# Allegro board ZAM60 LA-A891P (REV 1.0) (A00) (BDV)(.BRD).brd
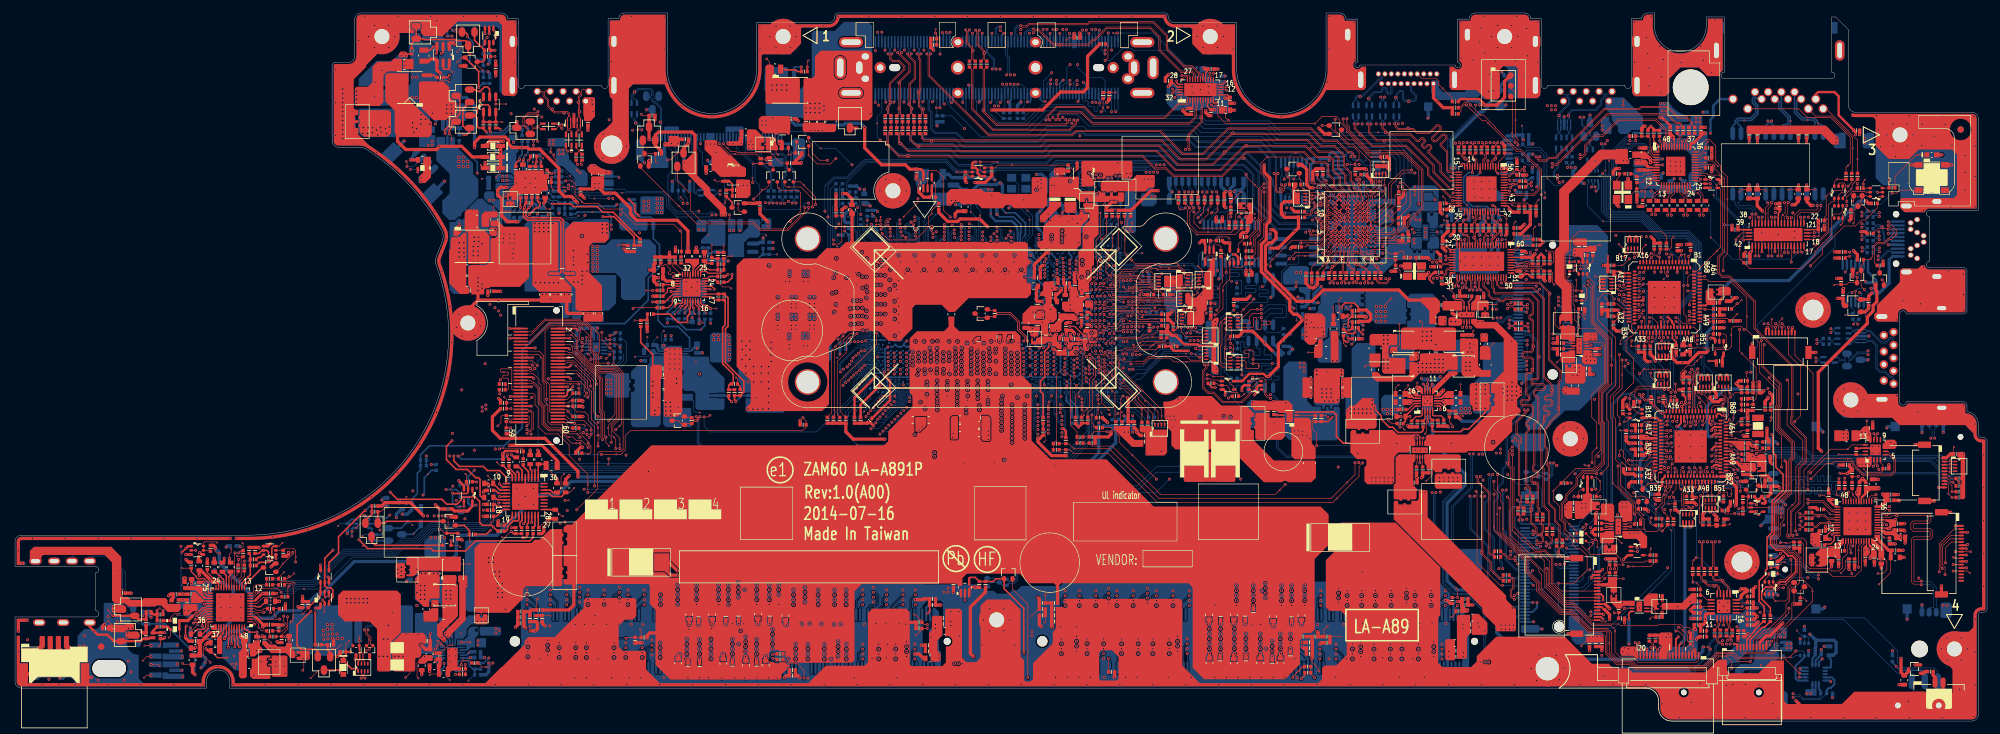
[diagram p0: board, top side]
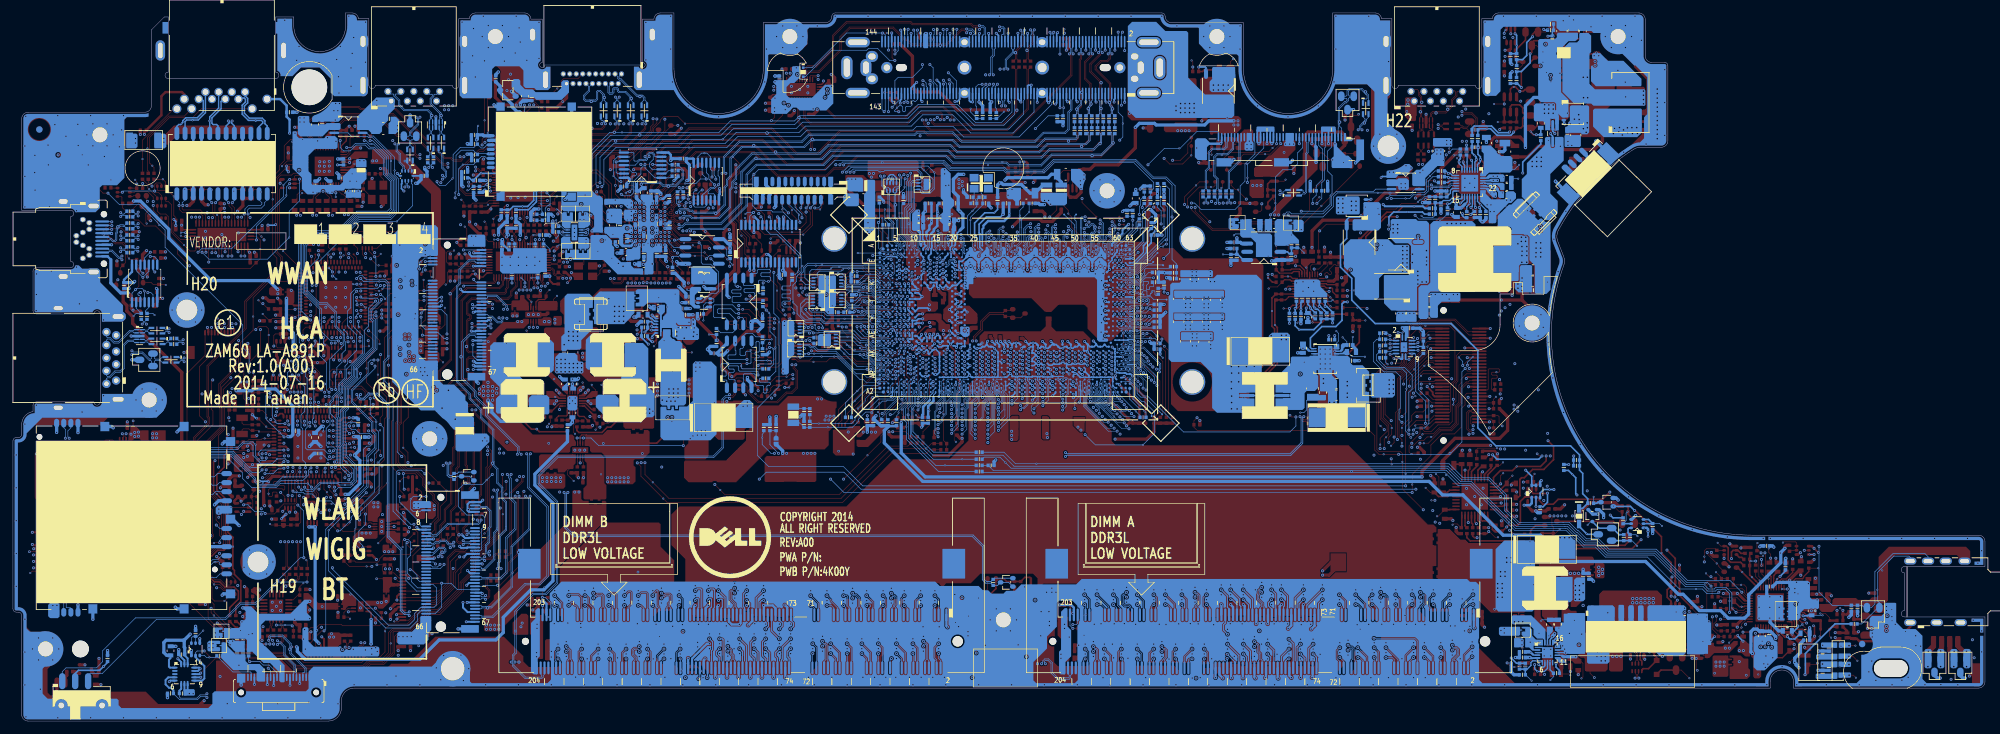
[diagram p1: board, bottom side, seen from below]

Outline 304.75 x 109.5 mm; copper layers: TOP, GND1, IN1, VCC, IN2, IN3, GND2, IN4, GND3, BOTTOM. Coordinates in mm from the lower left corner of the outline.
Outline path: 0,27.75 0,23.9 12.45,23.9 arc(12.95,23.4) 12.45,22.9 12.45,17.1 arc(12.95,16.6) 12.45,16.1 0,16.1 0,6.1 arc(0.29,5.39) 1,5.1 29.6,5.1 29.6,6.1 arc(31.4,7.9) 33.2,6.1 33.2,5.1 252,5.1 arc(253.41,4.51) 254,3.1 254,2 arc(254.59,0.59) 256,0 302.4,0 arc(303.11,0.29) 303.4,1 303.4,16.35 arc(303.55,16.7) 303.9,16.85 304.25,16.85 arc(304.6,16.99) 304.75,17.35 304.75,43.34 arc(304.6,43.69) 304.25,43.84 303.9,43.84 arc(303.55,43.99) 303.4,44.34 303.4,45.87 arc(302.9,47.19) 301.65,47.85 301.65,48.88 arc(301.49,49.21) 301.15,49.35 292.25,49.35 arc(291.75,48.85) 291.25,49.35 291.25,62.95 arc(291.75,63.45) 292.25,62.95 301.15,62.95 arc(301.5,63.1) 301.65,63.45 301.65,69.6 arc(301.5,69.95) 301.15,70.1 295.85,70.1 arc(295.35,70.6) 295.85,71.1 295.85,78 arc(295.35,78.5) 295.85,79 303.4,79 303.4,93.15 arc(303.11,93.86) 302.4,94.15 284.35,94.15 arc(283.64,94.44) 283.35,95.15 283.35,106.88 281.35,108.88 280.75,108.88 280.75,100.35 arc(281.25,99.87) 280.8,99.35 arc(280.77,99.35) 280.75,99.35 264.15,99.35 arc(264.13,99.35) 264.1,99.35 arc(263.65,99.87) 264.15,100.35 264.15,108.88 261.35,108.88 261.35,107.5 arc(257.35,103.5) 253.35,107.5 253.35,109.5 252.34,109.5 arc(251.67,109.24) 251.35,108.6 249.75,108.6 249.75,98.3 arc(249.25,97.8) 248.75,98.3 236.85,98.3 arc(236.35,97.8) 235.85,98.3 235.85,108.6 234.25,108.6 arc(233.93,109.24) 233.25,109.5 225.7,109.5 arc(225.01,109.22) 224.7,108.55 222.95,108.55 222.95,101.85 arc(223.23,101.17) 222.55,101.45 207.85,101.45 arc(207.17,101.17) 207.45,101.85 207.45,108.55 205.7,108.55 arc(205.39,109.22) 204.7,109.5 202.6,109.5 202.6,100.85 arc(195.7,93.95) 188.8,100.85 188.8,108 179.2,108 arc(178.49,108.29) 178.2,109 arc(178.05,109.35) 177.7,109.5 127.2,109.5 arc(126.85,109.35) 126.7,109 arc(126.41,108.29) 125.7,108 114.6,108 114.6,100.85 arc(107.7,93.95) 100.8,100.85 100.8,109.5 94.24,109.5 arc(93.57,109.24) 93.25,108.6 91.65,108.6 91.65,98.3 arc(91.15,97.8) 90.65,98.3 78.75,98.3 arc(78.25,97.8) 77.75,98.3 77.75,108.6 76.15,108.6 arc(75.83,109.24) 75.15,109.5 53.5,109.5 arc(52.79,109.21) 52.5,108.5 52.5,102.85 arc(52.21,102.14) 51.5,101.85 49.5,101.85 arc(49.15,101.7) 49,101.35 49,89.73 arc(49.29,89.03) 50,88.73 53.2,88.73 arc(53.76,88.65) 54.28,88.42 arc(60.9,82.9) 65.92,75.89 arc(66.16,75.07) 66.03,74.22 65.11,71.85 arc(64.98,71.14) 65.1,70.44 arc(61.42,42.01) 36,28.75 1,28.75 arc(0.29,28.46) 0,27.75

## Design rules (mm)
net group 10: nets SPI_DO64 SPI_PCH_DO2_64
net group 12: nets PCH_OPI_COMP PCH_PCIE_RCOMP
net group 20: nets SPI_PCH_CLK TDI_IREF
net group CLK_PCIE_LAN: nets CLK_PCIE_LAN CLK_PCIE_LAN#
net group CLK_PCIE_MMI: nets CLK_PCIE_MMI CLK_PCIE_MMI#
net group CLK_PCIE_SATA: nets CLK_PCIE_SATA CLK_PCIE_SATA#
net group CLK_PCIE_WIGIG: nets CLK_PCIE_WIGIG CLK_PCIE_WIGIG#
net group CLK_PCIE_WLAN: nets CLK_PCIE_WLAN CLK_PCIE_WLAN#
net group CPU_DPB_AUX: nets CPU_DPB_AUX CPU_DPB_AUX#
net group CPU_DPC_AUX: nets CPU_DPC_AUX CPU_DPC_AUX#
net group CPU_DPC_AUX_C: nets CPU_DPC_AUX#_C CPU_DPC_AUX_C
net group CRT-SYNC: nets HSYNC_DOCK VSYNC_DOCK
net group DDR_A_DQS0: nets DDR_A_DQS0 DDR_A_DQS#0
net group DDR_A_DQS1: nets DDR_A_DQS1 DDR_A_DQS#1
net group DDR_A_DQS2: nets DDR_A_DQS2 DDR_A_DQS#2
net group DDR_A_DQS3: nets DDR_A_DQS3 DDR_A_DQS#3
net group DDR_A_DQS4: nets DDR_A_DQS4 DDR_A_DQS#4
net group DDR_A_DQS5: nets DDR_A_DQS5 DDR_A_DQS#5
net group DDR_A_DQS6: nets DDR_A_DQS6 DDR_A_DQS#6
net group DDR_A_DQS7: nets DDR_A_DQS7 DDR_A_DQS#7
net group DDR_B_DQS0: nets DDR_B_DQS0 DDR_B_DQS#0
net group DDR_B_DQS1: nets DDR_B_DQS1 DDR_B_DQS#1
net group DDR_B_DQS2: nets DDR_B_DQS2 DDR_B_DQS#2
net group DDR_B_DQS3: nets DDR_B_DQS3 DDR_B_DQS#3
net group DDR_B_DQS4: nets DDR_B_DQS4 DDR_B_DQS#4
net group DDR_B_DQS5: nets DDR_B_DQS5 DDR_B_DQS#5
net group DDR_B_DQS6: nets DDR_B_DQS6 DDR_B_DQS#6
net group DDR_B_DQS7: nets DDR_B_DQS7 DDR_B_DQS#7
net group DOCK_DCIN_IS: nets DOCK_DCIN_IS+ DOCK_DCIN_IS-
net group DOCK_USB3R1: nets DOCK_USB3RN1 DOCK_USB3RP1
net group DOCK_USB3T1: nets DOCK_USB3TN1 DOCK_USB3TP1
net group DOCK_USBP0: nets DOCK_USBP0+ DOCK_USBP0-
net group DOCK_USBP3: nets DOCK_USBP3+ DOCK_USBP3-
net group EDP_CPU_AUX_C: nets EDP_CPU_AUX#_C EDP_CPU_AUX_C
net group M_CLK_DDR0: nets M_CLK_DDR0 M_CLK_DDR#0
net group M_CLK_DDR1: nets M_CLK_DDR1 M_CLK_DDR#1
net group M_CLK_DDR2: nets M_CLK_DDR2 M_CLK_DDR#2
net group M_CLK_DDR3: nets M_CLK_DDR3 M_CLK_DDR#3
net group MDP_AUX_C: nets MDP_AUX#_C MDP_AUX_C
net group MEM_SMB: nets MEM_SMBCLK MEM_SMBDATA
net group PS8338_0: nets PS8338_N0 PS8338_P0
net group PS8338_0_C: nets PS8338_N0_C PS8338_P0_C
net group PS8338_1: nets PS8338_N1 PS8338_P1
net group PS8338_1_C: nets PS8338_N1_C PS8338_P1_C
net group PS8338_2: nets PS8338_N2 PS8338_P2
net group PS8338_2_C: nets PS8338_N2_C PS8338_P2_C
net group PS8338_3: nets PS8338_N3 PS8338_P3
net group PS8338_3_C: nets PS8338_N3_C PS8338_P3_C
net group PS8338_AUX: nets PS8338_AUX PS8338_AUX#
net group PS_USBP1_D: nets PS_USBP1_D+ PS_USBP1_D-
net group SATA_PRX_DTX_1: nets SATA_PRX_DTX_N1 SATA_PRX_DTX_P1
net group SATA_PRX_DTX_1_C: nets SATA_PRX_DTX_N1_C SATA_PRX_DTX_P1_C
net group SATA_PRX_DTX_1_RP: nets SATA_PRX_DTX_N1_RP SATA_PRX_DTX_P1_RP
net group SATA_PRX_DTX_1_RP_C: nets SATA_PRX_DTX_N1_RP_C SATA_PRX_DTX_P1_RP_C
net group SATA_PTX_DRX_1: nets SATA_PTX_DRX_N1 SATA_PTX_DRX_P1
net group SATA_PTX_DRX_1_C: nets SATA_PTX_DRX_N1_C SATA_PTX_DRX_P1_C
net group SATA_PTX_DRX_1_RP: nets SATA_PTX_DRX_N1_RP SATA_PTX_DRX_P1_RP
net group SATA_PTX_DRX_1_RP_C: nets SATA_PTX_DRX_N1_RP_C SATA_PTX_DRX_P1_RP_C
net group SD/MMCDAT: nets SD/MMCDAT0 SD/MMCDAT1
net group SENSE: nets VCCSENSE VSSSENSE
net group SML0_SMB: nets SML0_SMBCLK SML0_SMBDATA
net group SML1_SMB: nets SML1_SMBCLK SML1_SMBDATA
net group SW_DPB_AUX: nets SW_DPB_AUX SW_DPB_AUX#
net group SW_DPB_AUX_C: nets SW_DPB_AUX#_C SW_DPB_AUX_C
net group SW_DPC_AUX: nets SW_DPC_AUX SW_DPC_AUX#
net group SW_DPC_AUX_C: nets SW_DPC_AUX#_C SW_DPC_AUX_C
net group SW_USB3R1: nets SW_USB3RN1 SW_USB3RP1
net group SW_USB3T1: nets SW_USB3TN1 SW_USB3TP1
net group SW_USBP0: nets SW_USBP0+ SW_USBP0-
net group SW_USBP3: nets SW_USBP3+ SW_USBP3-
net group TMDS_CON_CLK: nets TMDS_CON_CLK TMDS_CON_CLK#
net group USB2.0: nets USBP4+ USBP4-
net group USB3R1: nets USB3RN1 USB3RP1
net group USB3R2: nets USB3RN2 USB3RP2
net group USB3R4: nets USB3RN4 USB3RP4
net group USB3RN1_D: nets USB3RN1_D- USB3RP1_D+
net group USB3RN2_D: nets USB3RN2_D- USB3RP2_D+
net group USB3RP4_D: nets USB3RN4_D- USB3RP4_D+
net group USB3T1: nets USB3TN1 USB3TP1
net group USB3T1_C: nets USB3TN1_C USB3TP1_C
net group USB3T2: nets USB3TN2 USB3TP2
net group USB3T2_C: nets USB3TN2_C USB3TP2_C
net group USB3T4: nets USB3TN4 USB3TP4
net group USB3T4_C: nets USB3TN4_C USB3TP4_C
net group USB3TN1_D: nets USB3TN1_D- USB3TP1_D+
net group USB3TN2_D: nets USB3TN2_D- USB3TP2_D+
net group USB3TP4_D: nets USB3TN4_D- USB3TP4_D+
net group USBP0: nets USBP0+ USBP0-
net group USBP0_D: nets USBP0_D+ USBP0_D-
net group USBP1: nets USBP1+ USBP1-
net group USBP1_R_D: nets USBP1_R_D+ USBP1_R_D-
net group USBP2: nets USBP2+ USBP2-
net group USBP3: nets USBP3+ USBP3-
net group USBP3_D: nets USBP3_D+ USBP3_D-
net group USBP4_D: nets USBP4_D+ USBP4_D-
net group USBP5: nets USBP5+ USBP5-
net group USBP5_D: nets USBP5_D+ USBP5_D-
net group USBP6: nets USBP6+ USBP6-
net group USBP7: nets USBP7+ USBP7-
net group VMM2320_AUX: nets VMM2320_AUX VMM2320_AUX#
net group VMM2320_AUX_C: nets VMM2320_AUX#_C VMM2320_AUX_C
net group WIGIG_AUX: nets WIGIG_AUX WIGIG_AUX#
net group WIGIG_AUX_C: nets WIGIG_AUX#_C WIGIG_AUX_C
net group 15: nets AUD_HP_OUT_L AUD_HP_OUT_L1 AUD_HP_OUT_R AUD_HP_OUT_R1 CFG_RCOMP CLK_BIASREF DAI_12MHZ# DSWODVREN H_VCCST_PWRGD H_VCCST_PWRGD_XDP INTRUDER# MEC_XTAL1 PCH_DPWROK PCH_INTVRMEN PCH_PCIE_WAKE# PCH_RSMRST# PCH_RSMRST#_Q PCH_RTCRST# PCH_RTCX1 PCH_RTCX1_R PCH_RTCX2 PCI_CLK_LPC_0 PCI_CLK_LPC_1 PM_APWROK PM_APWROK_R RESET_OUT# RSMRST# SIO_PWRBTN# SIO_RCIN# SIO_SLP_A# SRTCRST# SYS_PWROK SYS_RESET# XDP_DBRESET# XTAL24_IN XTAL24_OUT XTAL24_OUT_R
net group 18: nets H_CPU_SVIDALRT#
net group ASYNC: nets H_CATERR# H_CPUPWRGD H_PROCHOT# H_PROCHOT#_R H_THERMTRIP# H_THERMTRIP#_R PCH_JTAG_TCK PCH_JTAG_TDI PCH_JTAG_TDO PCH_JTAG_TMS PCH_PLTRST# PCH_PLTRST#_EC PLTRST_LAN# PLTRST_MMI# PLTRST_USH# THERMATRIP2# THERMATRIP3# XDP_RST#_R
net group CRT-DAC: nets BLUE_DOCK GREEN_DOCK RED_DOCK
net group DDI1: nets DDI1_LANE_N0 DDI1_LANE_N1 DDI1_LANE_N2 DDI1_LANE_N3 DDI1_LANE_P0 DDI1_LANE_P1 DDI1_LANE_P2 DDI1_LANE_P3 MDP_LANE_N0_C MDP_LANE_N1_C MDP_LANE_N2_C MDP_LANE_N3_C MDP_LANE_P0_C MDP_LANE_P1_C MDP_LANE_P2_C MDP_LANE_P3_C
net group DDI2: nets DDI2_LANE_N0 DDI2_LANE_N0_C DDI2_LANE_N1 DDI2_LANE_N1_C DDI2_LANE_N2 DDI2_LANE_N2_C DDI2_LANE_N3 DDI2_LANE_N3_C DDI2_LANE_P0 DDI2_LANE_P0_C DDI2_LANE_P1 DDI2_LANE_P1_C DDI2_LANE_P2 DDI2_LANE_P2_C DDI2_LANE_P3 DDI2_LANE_P3_C
net group DDRA_CMD: nets DDR_A_BS0 DDR_A_BS1 DDR_A_BS2 DDR_A_CAS# DDR_A_MA0 DDR_A_MA1 DDR_A_MA2 DDR_A_MA3 DDR_A_MA4 DDR_A_MA5 DDR_A_MA6 DDR_A_MA7 DDR_A_MA8 DDR_A_MA9 DDR_A_MA10 DDR_A_MA11 DDR_A_MA12 DDR_A_MA13 DDR_A_MA14 DDR_A_MA15 DDR_A_RAS# DDR_A_WE#
net group DDRA_CTL: nets DDR_CKE0_DIMMA DDR_CKE1_DIMMA DDR_CS0_DIMMA# DDR_CS1_DIMMA# M_ODT0 M_ODT1
net group DDRA_D0: nets DDR_A_D0 DDR_A_D1 DDR_A_D2 DDR_A_D3 DDR_A_D4 DDR_A_D5 DDR_A_D6 DDR_A_D7
net group DDRA_D1: nets DDR_A_D8 DDR_A_D9 DDR_A_D10 DDR_A_D11 DDR_A_D12 DDR_A_D13 DDR_A_D14 DDR_A_D15
net group DDRA_D2: nets DDR_A_D16 DDR_A_D17 DDR_A_D18 DDR_A_D19 DDR_A_D20 DDR_A_D21 DDR_A_D22 DDR_A_D23
net group DDRA_D3: nets DDR_A_D24 DDR_A_D25 DDR_A_D26 DDR_A_D27 DDR_A_D28 DDR_A_D29 DDR_A_D30 DDR_A_D31
net group DDRA_D4: nets DDR_A_D32 DDR_A_D33 DDR_A_D34 DDR_A_D35 DDR_A_D36 DDR_A_D37 DDR_A_D38 DDR_A_D39
net group DDRA_D5: nets DDR_A_D40 DDR_A_D41 DDR_A_D42 DDR_A_D43 DDR_A_D44 DDR_A_D45 DDR_A_D46 DDR_A_D47
net group DDRA_D6: nets DDR_A_D48 DDR_A_D49 DDR_A_D50 DDR_A_D51 DDR_A_D52 DDR_A_D53 DDR_A_D54 DDR_A_D55
net group DDRA_D7: nets DDR_A_D56 DDR_A_D57 DDR_A_D58 DDR_A_D59 DDR_A_D60 DDR_A_D61 DDR_A_D62 DDR_A_D63
net group DDRB_CMD: nets DDR_B_BS0 DDR_B_BS1 DDR_B_BS2 DDR_B_CAS# DDR_B_MA0 DDR_B_MA1 DDR_B_MA2 DDR_B_MA3 DDR_B_MA4 DDR_B_MA5 DDR_B_MA6 DDR_B_MA7 DDR_B_MA8 DDR_B_MA9 DDR_B_MA10 DDR_B_MA11 DDR_B_MA12 DDR_B_MA13 DDR_B_MA14 DDR_B_MA15 DDR_B_RAS# DDR_B_WE#
net group DDRB_CTL: nets DDR_CKE2_DIMMB DDR_CKE3_DIMMB DDR_CS2_DIMMB# DDR_CS3_DIMMB# M_ODT2 M_ODT3
net group DDRB_D0: nets DDR_B_D0 DDR_B_D1 DDR_B_D2 DDR_B_D3 DDR_B_D4 DDR_B_D5 DDR_B_D6 DDR_B_D7
net group DDRB_D1: nets DDR_B_D8 DDR_B_D9 DDR_B_D10 DDR_B_D11 DDR_B_D12 DDR_B_D13 DDR_B_D14 DDR_B_D15
net group DDRB_D2: nets DDR_B_D16 DDR_B_D17 DDR_B_D18 DDR_B_D19 DDR_B_D20 DDR_B_D21 DDR_B_D22 DDR_B_D23
net group DDRB_D3: nets DDR_B_D24 DDR_B_D25 DDR_B_D26 DDR_B_D27 DDR_B_D28 DDR_B_D29 DDR_B_D30 DDR_B_D31
net group DDRB_D4: nets DDR_B_D32 DDR_B_D33 DDR_B_D34 DDR_B_D35 DDR_B_D36 DDR_B_D37 DDR_B_D38 DDR_B_D39
net group DDRB_D5: nets DDR_B_D40 DDR_B_D41 DDR_B_D42 DDR_B_D43 DDR_B_D44 DDR_B_D45 DDR_B_D46 DDR_B_D47
net group DDRB_D6: nets DDR_B_D48 DDR_B_D49 DDR_B_D50 DDR_B_D51 DDR_B_D52 DDR_B_D53 DDR_B_D54 DDR_B_D55
net group DDRB_D7: nets DDR_B_D56 DDR_B_D57 DDR_B_D58 DDR_B_D59 DDR_B_D60 DDR_B_D61 DDR_B_D62 DDR_B_D63
net group DMIC: nets DMIC0 DMIC1 DMIC_CLK0 DMIC_CLK1
net group DP: nets VMM2320_N0 VMM2320_N0_C VMM2320_N1 VMM2320_N1_C VMM2320_N2 VMM2320_N2_C VMM2320_N3 VMM2320_N3_C VMM2320_P0 VMM2320_P0_C VMM2320_P1 VMM2320_P1_C VMM2320_P2 VMM2320_P2_C VMM2320_P3 VMM2320_P3_C
net group DPB: nets DPB_DOCK_AUX DPB_DOCK_AUX# DPB_DOCK_LANE_N0 DPB_DOCK_LANE_N1 DPB_DOCK_LANE_N2 DPB_DOCK_LANE_N3 DPB_DOCK_LANE_P0 DPB_DOCK_LANE_P1 DPB_DOCK_LANE_P2 DPB_DOCK_LANE_P3 DPB_LANE_N0 DPB_LANE_N0_C DPB_LANE_N1 DPB_LANE_N1_C DPB_LANE_N2 DPB_LANE_N2_C DPB_LANE_N3 DPB_LANE_N3_C DPB_LANE_P0 DPB_LANE_P0_C DPB_LANE_P1 DPB_LANE_P1_C DPB_LANE_P2 DPB_LANE_P2_C DPB_LANE_P3 DPB_LANE_P3_C
net group DPC: nets DPC_DOCK_AUX DPC_DOCK_AUX# DPC_DOCK_LANE_N0 DPC_DOCK_LANE_N1 DPC_DOCK_LANE_N2 DPC_DOCK_LANE_N3 DPC_DOCK_LANE_P0 DPC_DOCK_LANE_P1 DPC_DOCK_LANE_P2 DPC_DOCK_LANE_P3 DPC_LANE_N0 DPC_LANE_N0_C DPC_LANE_N1 DPC_LANE_N1_C DPC_LANE_N2 DPC_LANE_N2_C DPC_LANE_N3 DPC_LANE_N3_C DPC_LANE_P0 DPC_LANE_P0_C DPC_LANE_P1 DPC_LANE_P1_C DPC_LANE_P2 DPC_LANE_P2_C DPC_LANE_P3 DPC_LANE_P3_C
net group EDP: nets EDP_CPU_AUX EDP_CPU_AUX# EDP_CPU_LANE_N0 EDP_CPU_LANE_N0_C EDP_CPU_LANE_N1 EDP_CPU_LANE_N1_C EDP_CPU_LANE_P0 EDP_CPU_LANE_P0_C EDP_CPU_LANE_P1 EDP_CPU_LANE_P1_C
net group HDA: nets PCH_AZ_BITCLK PCH_AZ_CODEC_BITCLK PCH_AZ_CODEC_RST# PCH_AZ_CODEC_SDIN0 PCH_AZ_CODEC_SDOUT PCH_AZ_CODEC_SYNC PCH_AZ_RST# PCH_AZ_SDIN0_R PCH_AZ_SDOUT PCH_AZ_SYNC
net group HDMI: nets HDMI_LANE_N0 HDMI_LANE_N1 HDMI_LANE_N2 HDMI_LANE_N3 HDMI_LANE_P0 HDMI_LANE_P1 HDMI_LANE_P2 HDMI_LANE_P3 TMDS_CON_N0 TMDS_CON_N1 TMDS_CON_N2 TMDS_CON_P0 TMDS_CON_P1 TMDS_CON_P2
net group LAN: nets LAN_TX0+ LAN_TX0+L LAN_TX0- LAN_TX0-L LAN_TX1+ LAN_TX1+L LAN_TX1- LAN_TX1-L LAN_TX2+ LAN_TX2+L LAN_TX2- LAN_TX2-L LAN_TX3+ LAN_TX3+L LAN_TX3- LAN_TX3-L
net group LAN_SW: nets DOCK_LOM_TRD0+ DOCK_LOM_TRD0- DOCK_LOM_TRD1+ DOCK_LOM_TRD1- DOCK_LOM_TRD2+ DOCK_LOM_TRD2- DOCK_LOM_TRD3+ DOCK_LOM_TRD3- SW_LAN_TX0+ SW_LAN_TX0- SW_LAN_TX1+ SW_LAN_TX1- SW_LAN_TX2+ SW_LAN_TX2- SW_LAN_TX3+ SW_LAN_TX3-
net group PCIE: nets PCIE_PRX_GLANTX_N3 PCIE_PRX_GLANTX_N3_C PCIE_PRX_GLANTX_P3 PCIE_PRX_GLANTX_P3_C PCIE_PRX_MMITX_N1 PCIE_PRX_MMITX_N1_C PCIE_PRX_MMITX_P1 PCIE_PRX_MMITX_P1_C PCIE_PRX_SATATX_N6_L0 PCIE_PRX_SATATX_N6_L1 PCIE_PRX_SATATX_P6_L0 PCIE_PRX_SATATX_P6_L1 PCIE_PRX_WIGIGTX_N5 PCIE_PRX_WIGIGTX_P5 PCIE_PRX_WLANTX_N4 PCIE_PRX_WLANTX_P4 PCIE_PTX_GLANRX_N3 PCIE_PTX_GLANRX_N3_C PCIE_PTX_GLANRX_P3 PCIE_PTX_GLANRX_P3_C PCIE_PTX_MMIRX_N1 PCIE_PTX_MMIRX_N1_C PCIE_PTX_MMIRX_P1 PCIE_PTX_MMIRX_P1_C PCIE_PTX_SATARX_N6_L0 PCIE_PTX_SATARX_N6_L0_C PCIE_PTX_SATARX_N6_L1 PCIE_PTX_SATARX_N6_L1_C PCIE_PTX_SATARX_P6_L0 PCIE_PTX_SATARX_P6_L0_C PCIE_PTX_SATARX_P6_L1 PCIE_PTX_SATARX_P6_L1_C PCIE_PTX_WIGIGRX_N5 PCIE_PTX_WIGIGRX_N5_C PCIE_PTX_WIGIGRX_P5 PCIE_PTX_WIGIGRX_P5_C PCIE_PTX_WLANRX_N4 PCIE_PTX_WLANRX_N4_C PCIE_PTX_WLANRX_P4 PCIE_PTX_WLANRX_P4_C
net group RJ45: nets NB_LAN_TX0+ NB_LAN_TX0- NB_LAN_TX1+ NB_LAN_TX1- NB_LAN_TX2+ NB_LAN_TX2- NB_LAN_TX3+ NB_LAN_TX3-
net group SATA: nets SATA_PRX_DKTX_N0 SATA_PRX_DKTX_N0_C SATA_PRX_DKTX_P0 SATA_PRX_DKTX_P0_C SATA_PTX_DKRX_N0 SATA_PTX_DKRX_N0_C SATA_PTX_DKRX_P0 SATA_PTX_DKRX_P0_C
net group SD-CARD: nets SD/MMCCD# SD/MMCCLK SD/MMCCLK_R SD/MMCCMD SD/MMCDAT2 SD/MMCDAT2_R SD/MMCDAT3 SD/MMCDAT3_R SD_REXT SD_UHS2_D0N SD_UHS2_D0P SD_UHS2_D1N SD_UHS2_D1P SDWP
net group SINGLE-CLK: nets CLK_PCI_DOCK CLK_PCI_LPDEBUG CLK_PCI_MEC CLK_PCI_SIO
net group SMBUS: nets CHARGER_SMBCLK CHARGER_SMBDAT CLK_KBD CLK_MSE CLK_TP_SIO DAT_KBD DAT_MSE DAT_TP_SIO DDR_XDP_WAN_SMBCLK DDR_XDP_WAN_SMBDAT DOCK_SMB_CLK DOCK_SMB_DAT GPU_SMBCLK GPU_SMBDAT PBAT_SMBCLK PBAT_SMBDAT USH_SMBCLK USH_SMBDAT
net group SPI: nets PCH_SPI_CLK PCH_SPI_CS0# PCH_SPI_CS1# PCH_SPI_DIN PCH_SPI_DO PCH_SPI_DO2 PCH_SPI_DO3 SPI_CLK32 SPI_CLK64 SPI_DIN32 SPI_DIN64 SPI_DO32 SPI_PCH_CS0# SPI_PCH_CS0#_R SPI_PCH_CS1# SPI_PCH_CS1#_R SPI_PCH_DIN SPI_PCH_DO SPI_PCH_DO2 SPI_PCH_DO2_32 SPI_PCH_DO3 SPI_PCH_DO3_32 SPI_PCH_DO3_64
net group SPK: nets INT_SPK_L+ INT_SPK_L- INT_SPK_R+ INT_SPK_R- INT_SPKR_L+ INT_SPKR_L- INT_SPKR_R+ INT_SPKR_R-
net group SVID: nets VIDALERT_N VIDSCLK VIDSOUT
net group THERMAL: nets REM_DIODE1_N REM_DIODE1_P REM_DIODE2_N REM_DIODE2_P REM_DIODE4_N REM_DIODE4_P
net group WIGIG: nets WIGIG_LANE_N0 WIGIG_LANE_N0_C WIGIG_LANE_N1 WIGIG_LANE_N1_C WIGIG_LANE_N2 WIGIG_LANE_N2_C WIGIG_LANE_N3 WIGIG_LANE_N3_C WIGIG_LANE_P0 WIGIG_LANE_P0_C WIGIG_LANE_P1 WIGIG_LANE_P1_C WIGIG_LANE_P2 WIGIG_LANE_P2_C WIGIG_LANE_P3 WIGIG_LANE_P3_C
nets with their own width: min track width 0.254; nets AUD_SENSE_A AUD_SENSE_B BAT1_LED# BAT2_LED# BATT_WHITE# BATT_YELLOW#
nets with their own width: min track width 0.381; nets +PCH_RTC_VCCSUS3_3 +PCH_VCCDSW3_3 AUD_OUT_L AUD_OUT_R PROC_OPI_RCOMP SATA_COMP SM_RCOMP0 SM_RCOMP1 SM_RCOMP2
nets with their own width: min track width 0.508; nets +0.9V_LAN +1.2V_LDO +1.05V_M +1.05V_MODPHY +1.05V_MODPHY_PCH +1.05V_MP +1.05V_RUN +1.5V_RUN +1.5V_RUN_AUDIO +1.05V_RUN_UZ7 +1.05V_RUN_VMM +1.05V_VCCST +1.05V_VMM_UV10 +1.05V_VMM_VDD +1.05V_VMM_VDDTX +1.8V_RUN_CARD +1.35V_MEM +1.35V_MEN_P +3.3V_ALW +3.3V_ALW2 +3.3V_ALW_DEG +3.3V_ALW_PCH +3.3V_ALW_PCH_UZ8 +3.3V_ALW_UE1 +3.3V_ALW_UE2 +3.3V_ALWP +3.3V_CAM +3.3V_M +3.3V_M_TPM +3.3V_RTC_LDO +3.3V_RUN +3.3V_RUN_AUDIO +3.3V_RUN_UZ9 +3.3V_RUN_VDDA +3.3V_RUN_VDDIO +3.3V_RUN_VMM +3.3V_SPI +3.3V_SUS +3.3V_TP +3.3V_VMM_UV10 +3.3V_WLAN_UL3 +3.3V_WWAN_UZ2 +5V_ALW +5V_ALW2 +5V_ALWP +5V_RUN +5V_RUN_UZ9 +AUX_LDO +CAP_LDO +COINCELL +DC_IN +DC_IN_SS +DCIN +DCIN_JACK +DCPRRTC +DIMM1_VREF_DQ +DIMM2_VREF_DQ +DOCK_PWR_BAR +GND_CHASSIS +LOM_VCT +MIC1_VREF_OUT +NBDOCK_DC_IN_SS +PBATT +PCH_ASATA3PLL +PCH_AUSB3PLL +PCH_VCC1P05 +PCH_VCCACLKPLL +PCH_VCCDSW +PCH_VCCDSW_R +RTC_CELL +RTC_CELL_VBAT +SIM_PWR +SM_VREF_CA +SM_VREF_CA_DIMM +SM_VREF_DQ0 +SM_VREF_DQ1 +USB_RIGHT_PWR +V1.05S_APLLOPI +V_DDR_REF +VCC_CORE +VCCIO_OUT +VCCIOA_OUT +VDDA_AVDD1 +VDDA_PVDD +VDISPLAY_VCC +VHDMI_VCC +VLDOIN_1.35V +VR_CAP +VREFOUT BQ24770_REGN EDP_COMP GND GNDA N33048 N33050
nets with their own width: min track width 0.635; nets +5V_RUN_AUDIO
nets with their own width: min track width 1.016; nets +3.3V_RUN_CARD +BL_PWR_SRC
nets with their own width: min track width 1.27; nets RING2 SLEEVE
nets with their own width: min track width 1.524; nets +0.675V_DDR_VTT +0.675V_P +3.3V_HDD +3.3V_LAN +3.3V_MMI
nets with their own width: min track width 2.032; nets +3.3V_WLAN +3.3V_WWAN +5V_HDD +5V_USB_CHG_PWR +LCDVDD +USB_LEFT_PWR

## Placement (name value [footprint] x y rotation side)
C33  4.7U_0805_25V6-K  [C_0805]  126.09 93.54 270 top
C42  4.7P_0402_50V8C  [C_0402]  153.73 93.18 90 bottom
C43  4.7P_0402_50V8C  [C_0402]  154.9 93.18 90 bottom
C263  1U_0402_6.3V6K  [C_0402]  232.99 90.64 0 bottom
C294  0.1U_0402_10V7K  [C_0402]  134.48 90.84 90 top
C295  0.1U_0402_10V7K  [C_0402]  135.37 91.75 270 bottom
C296  0.1U_0402_10V7K  [C_0402]  135.37 90.84 90 top
C297  0.1U_0402_10V7K  [C_0402]  136.25 91.75 270 bottom
C298  0.1U_0402_10V7K  [C_0402]  136.25 90.84 90 top
C299  0.1U_0402_10V7K  [C_0402]  137.14 91.75 270 bottom
C300  0.1U_0402_10V7K  [C_0402]  139.81 91.75 270 bottom
C301  0.1U_0402_10V7K  [C_0402]  140.7 91.75 270 bottom
C302  0.1U_0402_10V7K  [C_0402]  134.48 91.75 270 bottom
C303  0.1U_0402_10V7K  [C_0402]  137.14 90.84 90 top
C304  0.1U_0402_10V7K  [C_0402]  138.03 91.75 270 bottom
C305  0.1U_0402_10V7K  [C_0402]  138.03 90.84 90 top
C306  0.1U_0402_10V7K  [C_0402]  138.92 91.75 270 bottom
C307  0.1U_0402_10V7K  [C_0402]  138.92 90.84 90 top
C308  0.1U_0402_10V7K  [C_0402]  139.81 90.84 90 top
C309  0.1U_0402_10V7K  [C_0402]  140.7 90.84 90 top
C310  0.033U_0402_16V7K  [C_0402]  142.48 93.59 270 bottom
C311  0.033U_0402_16V7K  [C_0402]  142.43 105.52 180 top
C312  0.01U_0402_16V7K  [C_0402]  147.49 101.12 90 top
C313  0.01U_0402_16V7K  [C_0402]  148.38 101.12 90 top
C314  0.01U_0402_16V7K  [C_0402]  149.27 102.04 270 top
C315  0.01U_0402_16V7K  [C_0402]  150.16 102.04 270 top
C316  1U_0402_6.3V6K  [C_0402]  163.67 105.65 0 top
C317  0.1U_0603_50V7K  [C_0603]  123.3 93.39 270 top
C318  0.1U_0603_50V7K  [C_0603]  124.57 93.39 270 top
C319  4.7P_0402_50V8C  [C_0402]  169.1 97.21 270 top
CA1  680P_0402_50V7K  [C_0402]  25.26 17.83 90 top
CA2  220P_0402_50V7K  [C_0402]  20.25 15.73 270 top
CA3  220P_0402_50V7K  [C_0402]  20.24 12.73 90 top
CA4  680P_0402_50V7K  [C_0402]  26.6 17.83 90 top
CA5  100P_0402_50V8J  [C_0402]  103.35 82 0 bottom
CA6  100P_0402_50V8J  [C_0402]  102.49 82 180 bottom
CA8  0.1U_0402_25V6  [C_0402]  28.37 20.54 90 top
CA9  10U_0603_6.3V6M  [C_0603]  27.29 20.56 90 top
CA10  4.7U_0603_6.3V6K  [C_0603]  42.35 11.79 90 top
CA11  0.1U_0402_25V6  [C_0402]  38.9 14.9 0 top
CA12  680P_0402_50V7K  [C_0402]  16.13 19.79 0 top
CA13  680P_0402_50V7K  [C_0402]  14.45 14.31 180 top
CA16  4.7U_0603_6.3V6K  [C_0603]  31.63 10.86 180 top
CA17  0.1U_0402_25V6  [C_0402]  28.33 12.36 180 top
CA18  4.7U_0603_6.3V6K  [C_0603]  28.57 11.28 180 top
CA19  1000P_0402_50V7K  [C_0402]  25.08 9.93 90 bottom
CA22  1000P_0402_50V7K  [C_0402]  25.08 6.95 90 bottom
CA23  1000P_0402_50V7K  [C_0402]  24.13 8.75 270 bottom
CA24  1000P_0402_50V7K  [C_0402]  24.13 11.73 270 bottom
CA25  10U_0603_6.3V6M  [C_0603]  26.79 16.36 90 bottom
CA26  1U_0603_10V4Z  [C_0603]  28.47 23.3 90 top
CA27  0.1U_0402_25V6  [C_0402]  39.81 21.06 180 top
CA28  0.1U_0402_25V6  [C_0402]  39.81 22.02 180 top
CA29  1U_0603_10V6K  [C_0603]  27.18 13.44 0 top
CA30  22P_0402_50V8J  [C_0402]  41.21 13.07 270 top
CA31  1U_0603_10V6K  [C_0603]  37.39 13.06 270 top
CA33  15P_0402_50V8J  [C_0402]  40.87 17.38 0 top
CA35  2.2U_0402_6.3V6M  [C_0402]  27.23 24.56 270 top
CA41  0.1U_0402_25V6  [C_0402]  19.7 17.91 270 bottom
CA43  4.7U_0603_6.3V6K  [C_0603]  33.32 23.1 90 top
CA44  4.7U_0603_6.3V6K  [C_0603]  32.05 23.1 90 top
CA45  0.1U_0402_25V6  [C_0402]  35.34 11.67 0 top
CA46  10U_0603_6.3V6M  [C_0603]  34.5 13.89 270 bottom
CA47  0.1U_0402_25V6  [C_0402]  33.36 13.86 270 bottom
CA48  10U_0603_6.3V6M  [C_0603]  35.24 10.45 0 top
CA49  1U_0603_10V6K  [C_0603]  31.24 13.94 180 bottom
CA50  0.1U_0402_25V6  [C_0402]  38.9 19.73 0 top
CA51  4.7U_0603_6.3V6K  [C_0603]  30.78 23.1 90 top
CA52  4.7U_0603_6.3V6K  [C_0603]  28.5 13.59 180 bottom
CA53  4.7U_0603_6.3V6K  [C_0603]  38.78 18.52 0 top
CA54  22P_0402_50V8J  [C_0402]  40.75 13.94 90 top
CC1  12P_0402_50V8J  [C_0402]  182.5 47.4 90 bottom
CC2  12P_0402_50V8J  [C_0402]  182.5 46.34 270 bottom
CC3  1U_0402_6.3V6K  [C_0402]  172.72 45.68 90 bottom
CC4  1U_0402_6.3V6K  [C_0402]  186.81 45.83 270 bottom
CC5  27P_0402_50V8J  [C_0402]  154.05 39.54 180 bottom
CC6  0.1U_0402_25V6  [C_0402]  188.91 61.3 90 bottom
CC7  0.1U_0402_25V6  [C_0402]  195.95 56.87 0 bottom
CC8  15P_0402_50V8J  [C_0402]  153.96 80.06 0 bottom
CC9  33P_0402_50V8J  [C_0402]  188.91 56.67 90 bottom
CC10  33P_0402_50V8J  [C_0402]  196.02 57.94 90 bottom
CC11  15P_0402_50V8J  [C_0402]  157.29 81.01 180 bottom
CC12  12P_0402_50V8J  [C_0402]  162.39 43.81 270 top
CC13  12P_0402_50V8J  [C_0402]  162.39 41.03 90 top
CC14  12P_0402_50V8J  [C_0402]  166.91 42.99 180 top
CC15  12P_0402_50V8J  [C_0402]  166.91 43.94 180 top
CC17  0.1U_0402_25V6  [C_0402]  89.34 60.75 180 bottom
CC20  22P_0402_50V8J  [C_0402]  124.95 68.43 0 bottom
CC21  0.1U_0402_25V6  [C_0402]  86.2 49.58 0 top
CC22  0.1U_0402_25V6  [C_0402]  75.94 49.19 180 top
CC23  22U_0603_6.3V6M  [C_0603]  144.7 63.61 270 top
CC24  100P_0402_50V8J  [C_0402]  142.25 81 180 top
CC25  2.2U_0402_6.3V6M  [C_0402]  148.77 46.9 0 top
CC26  2.2U_0402_6.3V6M  [C_0402]  151.29 59.42 0 top
CC27  2.2U_0402_6.3V6M  [C_0402]  148.89 58.26 90 top
CC28  2.2U_0402_6.3V6M  [C_0402]  154.63 59.41 180 top
CC29  10U_0603_6.3V6M  [C_0603]  148.27 45.82 0 top
CC30  10U_0603_6.3V6M  [C_0603]  148.27 44.55 0 top
CC31  10U_0603_6.3V6M  [C_0603]  146.75 46.65 180 top
CC32  10U_0603_6.3V6M  [C_0603]  146.75 45.31 180 top
CC33  10U_0603_6.3V6M  [C_0603]  141.92 46.58 180 top
CC34  10U_0603_6.3V6M  [C_0603]  138.05 46.58 0 top
CC35  0.1U_0402_25V6  [C_0402]  139.32 85.33 270 top
CC36  22U_0603_6.3V6M  [C_0603]  156.14 60.81 90 top
CC37  1U_0402_6.3V6K  [C_0402]  158.05 60.73 90 top
CC39  330U_D3_2.5VY_R6M  [C_D2]  198.13 46.91 180 bottom
CC40  1U_0402_6.3V6K  [C_0402]  164.84 66.15 270 top
CC41  330U_D3_2.5VY_R6M  [C_D3]  187.05 44.58 270 top
CC42  330U_D3_2.5VY_R6M  [C_D3]  182.23 44.58 270 top
CC43  1U_0402_6.3V6K  [C_0402]  165.73 66.6 270 top
CC44  1U_0402_6.3V6K  [C_0402]  166.38 78.08 180 top
CC47  22U_0603_6.3V6M  [C_0603]  159.32 77.44 0 bottom
CC49  0.1U_0402_10V7K  [C_0402]  162.37 59.1 180 top
CC50  1U_0402_6.3V6K  [C_0402]  171.76 46.6 270 bottom
CC51  22U_0603_6.3V6M  [C_0603]  159.32 76.17 0 bottom
CC52  0.1U_0402_10V7K  [C_0402]  165.69 60.4 90 top
CC55  22U_0603_6.3V6M  [C_0603]  164.08 76.43 0 bottom
CC56  22U_0603_6.3V6M  [C_0603]  164.08 77.63 0 bottom
CC57  0.1U_0402_10V7K  [C_0402]  160.28 61.06 180 top
CC58  1U_0402_6.3V6K  [C_0402]  159.34 59.21 90 top
CC59  1U_0402_6.3V6K  [C_0402]  162.04 67.73 0 top
CC60  10U_0603_6.3V6M  [C_0603]  162.3 65.89 270 top
CC61  1U_0402_6.3V6K  [C_0402]  162.43 60.54 90 top
CC63  22U_0603_6.3V6M  [C_0603]  162.05 62.59 180 top
CC64  22U_0603_6.3V6M  [C_0603]  161.03 64.87 180 top
CC65  1U_0402_6.3V6K  [C_0402]  158.87 45.14 270 top
CC66  0.1U_0402_10V7K  [C_0402]  160.79 66.01 180 top
CC67  100U_1206_6.3V6M  [C_1206]  172.01 80.63 0 bottom
CC68  1U_0402_6.3V6K  [C_0402]  158.06 62.59 180 top
CC69  1U_0402_6.3V6K  [C_0402]  165.61 64.36 180 top
CC70  1U_0402_6.3V6K  [C_0402]  158.04 64.89 270 top
CC71  1U_0402_6.3V6K  [C_0402]  163.83 67.8 270 top
CC72  1U_0402_6.3V6K  [C_0402]  161.41 57.77 270 top
CC73  1U_0402_6.3V6K  [C_0402]  163.21 56.81 180 top
CC77  100U_1206_6.3V6M  [C_1206]  143.38 84.56 180 bottom
CC78  1U_0402_6.3V6K  [C_0402]  161.17 67.73 180 top
CC79  22U_0603_6.3V6M  [C_0603]  129.35 79.79 270 top
CC80  1U_0402_6.3V6K  [C_0402]  164.21 59.09 180 top
CC81  100U_1206_6.3V6M  [C_1206]  146.81 81.64 0 bottom
CC82  1U_0402_6.3V6K  [C_0402]  158.67 80.05 0 bottom
CC83  100P_0402_50V8J  [C_0402]  131.7 78.07 90 bottom
CC84  22U_0603_6.3V6M  [C_0603]  158.1 67.23 180 top
CC85  22U_0603_6.3V6M  [C_0603]  146.75 80.24 270 top
CC94  680P_0402_50V7K  [C_0402]  87.37 82.28 270 top
CC95  680P_0402_50V7K  [C_0402]  73.99 66.46 180 top
CC96  680P_0402_50V7K  [C_0402]  115.12 80.12 270 top
CC97  0.47U_0402_10V6K  [C_0402]  165.33 58.64 90 top
CC100  1U_0402_6.3V6K  [C_0402]  165.68 63.25 270 top
CD1  0.1U_0402_25V6  [C_0402]  78.62 15.15 180 top
CD2  1U_0402_6.3V6K  [C_0402]  116.63 16.69 270 top
CD3  1U_0402_6.3V6K  [C_0402]  111.81 16.69 270 top
CD4  1U_0402_6.3V6K  [C_0402]  109.84 16.63 270 top
CD5  2.2U_0402_6.3V6M  [C_0402]  78.62 16.04 180 top
CD6  0.1U_0402_25V6  [C_0402]  95.82 12.94 270 top
CD7  1U_0402_6.3V6K  [C_0402]  105.65 16.57 270 top
CD8  1U_0402_6.3V6K  [C_0402]  114.6 8.03 90 top
CD9  1U_0402_6.3V6K  [C_0402]  110.85 8.03 90 top
CD10  1U_0402_6.3V6K  [C_0402]  105.79 7.96 90 top
CD11  1U_0402_6.3V6K  [C_0402]  104.01 8.03 90 top
CD12  10U_0603_6.3V6M  [C_0603]  119.06 16.99 270 top
CD13  10U_0603_6.3V6M  [C_0603]  114.79 17.25 270 top
CD14  10U_0603_6.3V6M  [C_0603]  107.74 17.19 270 top
CD15  10U_0603_6.3V6M  [C_0603]  104.19 17.19 270 top
CD16  10U_0603_6.3V6M  [C_0603]  116 7.92 90 top
CD17  10U_0603_6.3V6M  [C_0603]  112.95 7.92 90 top
CD18  10U_0603_6.3V6M  [C_0603]  109.46 8.17 90 top
CD19  10U_0603_6.3V6M  [C_0603]  102.49 8.23 90 top
CD20  330U_D2_2V_Y  [C_D2]  93.56 24.55 0 top
CD21  0.022U_0402_16V7K  [C_0402]  80.52 15.39 90 top
CD22  0.1U_0402_25V6  [C_0402]  119.68 7.91 0 top
CD23  2.2U_0402_6.3V6M  [C_0402]  119.68 7.02 0 top
CD24  0.1U_0402_25V6  [C_0402]  141.6 10.78 180 top
CD25  0.1U_0402_25V6  [C_0402]  141.6 11.73 180 top
CD26  0.1U_0402_25V6  [C_0402]  143.05 15.91 0 top
CD27  0.1U_0402_25V6  [C_0402]  143.05 15.02 0 top
CD28  10U_0603_6.3V6M  [C_0603]  142.1 9.7 180 top
CD29  10U_0603_6.3V6M  [C_0603]  142.94 13.94 0 top
CD30  0.1U_0402_25V6  [C_0402]  145.02 21.58 270 top
CD31  2.2U_0402_6.3V6M  [C_0402]  142.25 18.9 180 top
CD32  0.1U_0402_25V6  [C_0402]  142.25 17.94 180 top
CD33  2.2U_0402_6.3V6M  [C_0402]  160.2 15.4 0 top
CD34  0.1U_0402_25V6  [C_0402]  160.2 16.36 0 top
CD35  0.1U_0402_25V6  [C_0402]  169.01 7.6 0 top
CD36  0.022U_0402_16V7K  [C_0402]  202.28 13.06 0 top
CD37  1U_0402_6.3V6K  [C_0402]  197.28 16.57 270 top
CD38  1U_0402_6.3V6K  [C_0402]  190.1 16.69 270 top
CD39  1U_0402_6.3V6K  [C_0402]  186.31 16.62 270 top
CD40  1U_0402_6.3V6K  [C_0402]  191.37 16.35 90 top
CD41  1U_0402_6.3V6K  [C_0402]  197.09 9.62 90 top
CD42  1U_0402_6.3V6K  [C_0402]  194.29 8.48 90 top
CD43  1U_0402_6.3V6K  [C_0402]  190.23 8.86 90 top
CD44  1U_0402_6.3V6K  [C_0402]  186.24 8.85 90 top
CD45  10U_0603_6.3V6M  [C_0603]  198.8 17.06 270 top
CD46  10U_0603_6.3V6M  [C_0603]  194.42 16.87 270 top
CD47  10U_0603_6.3V6M  [C_0603]  188.34 17.12 270 top
CD48  10U_0603_6.3V6M  [C_0603]  184.53 17.12 270 top
CD49  10U_0603_6.3V6M  [C_0603]  195.56 8.3 90 top
CD50  10U_0603_6.3V6M  [C_0603]  192.45 8.3 90 top
CD51  10U_0603_6.3V6M  [C_0603]  188.34 8.23 90 top
CD52  10U_0603_6.3V6M  [C_0603]  184.59 8.29 90 top
CD53  330U_D2_2V_Y  [C_D2]  201.57 28.4 0 top
CD54  0.022U_0402_16V7K  [C_0402]  158.29 17.31 0 top
CD55  0.1U_0402_25V6  [C_0402]  200.48 11.28 180 top
CD56  2.2U_0402_6.3V6M  [C_0402]  200.48 10.39 180 top
CD57  0.1U_0402_25V6  [C_0402]  223.14 9.95 180 top
CD58  0.1U_0402_25V6  [C_0402]  223.14 10.9 180 top
CD59  0.1U_0402_25V6  [C_0402]  224.51 13.95 0 top
CD60  0.1U_0402_25V6  [C_0402]  224.51 14.9 0 top
CD61  10U_0603_6.3V6M  [C_0603]  223.2 12.04 180 top
CD62  10U_0603_6.3V6M  [C_0603]  224.52 15.98 0 top
CD63  2.2U_0402_6.3V6M  [C_0402]  223.62 18.9 0 top
CD64  0.1U_0402_25V6  [C_0402]  223.62 17.95 0 top
CE1  10U_0603_6.3V6M  [C_0603]  264.65 66.34 270 top
CE2  0.1U_0402_25V6  [C_0402]  262.48 64.69 0 top
CE3  0.1U_0402_25V6  [C_0402]  256.9 72.74 90 top
CE4  0.1U_0402_10V7K  [C_0402]  247.07 69.51 180 top
CE5  0.1U_0402_25V6  [C_0402]  247.07 63.55 180 top
CE6  0.1U_0402_25V6  [C_0402]  256.71 58.1 270 top
CE7  4.7U_0603_6.3V6K  [C_0603]  257.79 58.08 270 top
CE8  0.047U_0402_16V4Z  [C_0402]  262.48 61.77 0 top
CE9  33P_0402_50V8J  [C_0402]  245.22 64.51 270 top
CE10  1U_0402_6.3V6K  [C_0402]  267.71 52.62 180 top
CE11  0.1U_0402_25V6  [C_0402]  261.5 44.93 180 bottom
CE12  1U_0402_6.3V6K  [C_0402]  266.81 50.77 90 top
CE13  0.1U_0402_25V6  [C_0402]  257.79 50.45 90 top
CE14  1U_0402_6.3V6K  [C_0402]  251.34 43.92 180 bottom
CE15  1U_0402_6.3V6K  [C_0402]  266.86 42.15 0 top
CE16  0.1U_0402_25V6  [C_0402]  251.34 41.12 180 top
CE17  0.1U_0402_25V6  [C_0402]  261.97 50.08 0 top
CE18  0.1U_0402_25V6  [C_0402]  267.01 39.04 270 top
CE19  0.1U_0402_25V6  [C_0402]  259.19 34.73 270 top
CE20  0.1U_0402_25V6  [C_0402]  266.86 43.03 0 top
CE21  10U_0603_6.3V6M  [C_0603]  269.86 40.75 0 top
CE22  0.1U_0402_25V6  [C_0402]  254.05 35.05 270 top
CE23  0.1U_0402_25V6  [C_0402]  251.33 43.92 180 top
CE24  2200P_0402_50V7K  [C_0402]  255.89 49.57 0 top
CE25  0.1U_0402_25V6  [C_0402]  266.01 33.95 180 top
CE26  2200P_0402_50V7K  [C_0402]  254.75 49.3 90 top
CE27  2200P_0402_50V7K  [C_0402]  252.85 50.15 270 top
CE28  33P_0402_50V8J  [C_0402]  267.71 44.94 270 top
CE29  33P_0402_50V8J  [C_0402]  267.76 45.82 90 top
CE30  1U_0402_6.3V6K  [C_0402]  260.84 30.32 90 top
CE31  4.7U_0603_6.3V6K  [C_0603]  258.06 44.55 270 bottom
CE32  10U_0603_6.3V6M  [C_0603]  63.65 86.78 180 top
CE34  4.7P_0402_50V8C  [C_0402]  249.49 38.97 180 top
CE35  100P_0402_50V8J  [C_0402]  151.4 63.48 270 top
CE36  0.1U_0402_25V6  [C_0402]  251.34 37.95 180 top
CE37  100P_0402_50V8J  [C_0402]  153.27 20.99 90 bottom
CE38  0.1U_0402_25V6  [C_0402]  251.33 45.77 180 top
CE39  100P_0402_50V8J  [C_0402]  104.58 46.91 270 top
CE40  4700P_0402_25V7K  [C_0402]  258.75 51.37 270 top
CE44  1U_0402_6.3V6K  [C_0402]  268.59 48.95 270 top
CE45  1U_0402_6.3V6K  [C_0402]  266.8 48.05 0 top
CE46  100P_0402_50V8J  [C_0402]  236.58 38.28 270 bottom
CI1  100U_1206_6.3V6M  [C_1206]  84.4 86.83 90 bottom
CI3  0.1U_0402_25V6  [C_0402]  88.53 93.04 270 top
CI4  0.1U_0402_10V7K  [C_0402]  86.71 87.67 270 top
CI5  0.1U_0402_10V7K  [C_0402]  87.63 87.65 270 top
CI6  10U_0603_6.3V6M  [C_0603]  89.66 83.79 90 top
CI7  0.1U_0402_25V6  [C_0402]  90.74 83.97 90 top
CI8  100U_1206_6.3V6M  [C_1206]  248.84 91.61 180 bottom
CI10  0.1U_0402_25V6  [C_0402]  247.01 93.14 180 bottom
CI11  10U_0603_6.3V6M  [C_0603]  258.05 91.55 90 bottom
CI12  0.1U_0402_25V6  [C_0402]  256.97 91.98 90 bottom
CI13  0.1U_0402_10V7K  [C_0402]  280.35 58.27 180 bottom
CI14  100U_1206_6.3V6M  [C_1206]  284.34 44.11 180 top
CI16  0.1U_0402_10V7K  [C_0402]  280.35 59.16 180 bottom
CI17  0.1U_0402_25V6K~D  [C_0402]  286.17 45.3 0 top
CI19  0.1U_0402_25V6K~D  [C_0402]  282.56 39.59 0 top
CI27  0.1U_0402_10V7K  [C_0402]  240.65 87.24 270 bottom
CI28  0.1U_0402_10V7K  [C_0402]  239.76 87.24 270 bottom
CI38  0.1U_0402_25V6  [C_0402]  241.68 84.31 180 bottom
CI414  0.1U_0402_25V6  [C_0402]  187.75 96.45 270 top
CI415  0.1U_0402_25V6  [C_0402]  184.38 100.82 0 top
CI416  0.1U_0402_25V6  [C_0402]  184.77 94.55 270 top
CI417  0.1U_0402_25V6  [C_0402]  186.29 98.83 90 bottom
CI418  0.1U_0402_25V6  [C_0402]  178.69 98.98 180 top
CI419  0.1U_0402_25V6  [C_0402]  181.78 94.74 270 top
CI420  4.7U_0603_6.3V6K  [C_0603]  186.37 94.46 0 top
CL1  0.1U_0402_10V7K  [C_0402]  259.57 90.9 90 top
CL2  0.1U_0402_10V7K  [C_0402]  258.68 90.9 90 top
CL3  0.1U_0402_10V7K  [C_0402]  258.05 82.58 90 bottom
CL4  10U_0603_6.3V6M  [C_0603]  252.85 82.65 270 bottom
CL5  0.1U_0402_10V7K  [C_0402]  257.79 91.82 270 top
CL6  0.1U_0402_10V7K  [C_0402]  256.9 91.82 270 top
CL7  1U_0603_10V6K  [C_0603]  251.84 87.22 90 top
CL8  0.1U_0402_10V7K  [C_0402]  255.78 90.89 90 top
CL9  0.1U_0402_10V7K  [C_0402]  260.52 90.9 90 top
CL10  0.1U_0402_10V7K  [C_0402]  253.46 83.99 0 bottom
CL11  0.1U_0402_10V7K  [C_0402]  255.63 82.58 90 bottom
CL12  22U_0603_6.3V6M  [C_0603]  251.39 82.65 270 bottom
CL13  27P_0402_50V8J  [C_0402]  247 84.62 0 top
CL14  27P_0402_50V8J  [C_0402]  250.63 81.37 90 top
CL15  0.1U_0402_10V7K  [C_0402]  278.67 75.99 0 top
CL16  0.47U_0603_10V7K  [C_0603]  276.91 82.21 270 top
CL17  0.47U_0603_10V7K  [C_0603]  275.57 82.21 270 top
CL18  470P_0402_50V7K  [C_0402]  262.46 94.14 180 bottom
CL19  0.1U_0402_10V7K  [C_0402]  284.15 91.35 0 top
CL20  0.47U_0603_10V7K  [C_0603]  269.22 82.21 270 top
CL21  0.47U_0603_10V7K  [C_0603]  267.95 82.21 270 top
CL22  150P_1808_2.5KV8J  [C_1808]  286.72 89.85 180 bottom
CL23  0.1U_0402_10V7K  [C_0402]  245.17 31.48 180 top
CL24  470P_0402_50V7K  [C_0402]  245.17 30.59 180 top
CL25  0.1U_0402_25V6  [C_0402]  268.09 71.86 180 top
CL26  0.1U_0402_25V6  [C_0402]  266.25 75.99 180 top
CL27  0.1U_0402_25V6  [C_0402]  272.72 79.15 90 top
CMOS1  SHORT PADS~D  [SHORTPADS-S]  186.81 43.28 90 bottom
CN1  10U_0603_6.3V6M  [C_0603]  280.4 10.16 90 bottom
CN2  0.1U_0402_25V6  [C_0402]  278.2 10.3 0 bottom
CN3  0.1U_0402_10V7K  [C_0402]  254.57 19.33 180 top
CN4  470P_0402_50V7K  [C_0402]  253.6 16.08 0 top
CN13  1000P_0402_50V7K  [C_0402]  269.22 10.07 90 bottom
CN14  0.1U_0402_25V6  [C_0402]  270.11 10.07 90 bottom
CN15  0.1U_0402_25V6  [C_0402]  270.11 13.01 270 bottom
CN16  0.1U_0402_25V6  [C_0402]  269.22 13.01 270 bottom
CN17  0.01U_0402_16V7K  [C_0402]  262.64 13.16 90 top
CN18  0.01U_0402_16V7K  [C_0402]  263.53 13.16 90 top
CN19  0.01U_0402_16V7K  [C_0402]  265.38 13.16 90 top
CN20  0.01U_0402_16V7K  [C_0402]  264.49 13.16 90 top
CN23  0.01U_0402_16V7K  [C_0402]  262.9 23.6 270 top
CN24  0.1U_0402_25V6  [C_0402]  260.41 14.9 180 top
CN25  0.01U_0402_16V7K  [C_0402]  261.06 23.6 270 top
CN26  0.01U_0402_16V7K  [C_0402]  260.17 23.6 270 top
CN29  0.01U_0402_16V7K  [C_0402]  267.7 20.17 0 top
CN30  0.01U_0402_16V7K  [C_0402]  262.01 23.6 270 top
CR1  4.7U_0603_6.3V6K  [C_0603]  290.7 28.42 0 top
CR2  0.1U_0402_25V6  [C_0402]  279.78 29.38 180 top
CR3  0.1U_0402_25V6  [C_0402]  290.42 29.51 0 top
CR4  0.1U_0402_25V6  [C_0402]  285.04 35.97 90 top
CR6  0.1U_0402_25V6  [C_0402]  287.33 25.64 270 top
CR7  4.7U_0603_6.3V6K  [C_0603]  280.72 24.75 90 top
CR8  0.1U_0402_25V6  [C_0402]  281.81 24.47 90 top
CR9  4.7U_0603_6.3V6K  [C_0603]  287.07 37.38 270 top
CR10  0.1U_0402_25V6  [C_0402]  285.99 36.89 270 top
CR13  0.1U_0402_25V6  [C_0402]  290.33 35.03 180 top
CR14  4.7U_0603_6.3V6K  [C_0603]  291.26 25.32 180 top
CR15  0.1U_0402_25V6  [C_0402]  291.02 26.4 180 top
CR17  1U_0402_6.3V6K  [C_0402]  278.75 27.22 0 top
CR18  4.7U_0603_6.3V6K  [C_0603]  278.38 28.3 0 top
CR19  0.1U_0402_25V6  [C_0402]  290.33 34.14 180 top
CR21  0.1U_0402_25V6  [C_0402]  280.27 35.17 270 top
CR22  0.1U_0402_25V6  [C_0402]  291.33 30.53 180 top
CR23  5P_0402_50V8C  [C_0402]  283.89 37.82 90 top
CR24  0.1U_0402_10V7K  [C_0402]  276.77 31.35 0 top
CR25  0.1U_0402_10V7K  [C_0402]  276.77 32.24 0 top
CR26  0.1U_0402_10V7K  [C_0402]  276.77 30.46 0 top
CR27  0.1U_0402_10V7K  [C_0402]  276.77 29.57 0 top
CR31  1U_0402_6.3V6K  [C_0402]  285.92 25.71 270 top
CR34  4.7U_0603_6.3V6K  [C_0603]  288.4 25.76 270 top
CR35  0.1U_0402_25V6  [C_0402]  274.9 27.67 270 top
CV1  0.1U_0402_10V7K  [C_0402]  116.39 81.05 90 bottom
CV2  0.1U_0402_10V7K  [C_0402]  117.28 81.05 90 bottom
CV3  0.1U_0402_10V7K  [C_0402]  118.17 81.05 90 bottom
CV4  0.1U_0402_10V7K  [C_0402]  119.06 81.05 90 bottom
CV5  0.1U_0402_10V7K  [C_0402]  119.95 81.05 90 bottom
CV6  0.1U_0402_10V7K  [C_0402]  120.84 81.05 90 bottom
CV9  10U_0603_6.3V6M  [C_0603]  113.66 91.03 180 top
CV10  0.01U_0402_16V7K  [C_0402]  119.49 93.13 0 top
CV11  1000P_0402_50V7K  [C_0402]  111.77 82.14 180 top
CV12  0.1U_0603_50V7K  [C_0603]  108.2 85.51 180 top
CV23  0.1U_0402_16V4Z  [C_0402]  230.15 98.86 90 bottom
CV26  0.1U_0402_10V7K  [C_0402]  224.57 96.86 270 bottom
CV27  10U_0603_6.3V6M  [C_0603]  225.64 97.33 270 bottom
CV60  2.2U_0402_6.3V6M  [C_0402]  230.17 87.85 90 top
CV61  0.01U_0402_16V7K  [C_0402]  227.01 77.13 270 bottom
CV62  0.01U_0402_16V7K  [C_0402]  221.17 79.1 180 top
CV66  0.1U_0402_25V6  [C_0402]  228.38 77.13 270 bottom
CV69  0.1U_0402_25V6  [C_0402]  235.4 84.91 180 bottom
CV71  0.1U_0402_25V6  [C_0402]  229.28 88.77 270 top
CV72  0.1U_0402_25V6  [C_0402]  228.39 88.77 270 top
CV73  0.1U_0402_25V6  [C_0402]  227.5 88.77 270 top
CV74  0.1U_0402_25V6  [C_0402]  226.62 88.77 270 top
CV75  0.1U_0402_25V6  [C_0402]  225.73 88.77 270 top
CV76  0.1U_0402_25V6  [C_0402]  224.84 88.77 270 top
CV77  0.1U_0402_25V6  [C_0402]  223.95 88.77 270 top
CV78  0.1U_0402_25V6  [C_0402]  223.06 88.77 270 top
CV79  0.1U_0402_25V6  [C_0402]  233.42 83.48 180 top
CV80  0.1U_0402_25V6  [C_0402]  233.42 82.6 180 top
CV82  10U_0603_6.3V6M  [C_0603]  207.25 81.01 90 bottom
CV83  0.1U_0402_25V6  [C_0402]  206.17 81.06 90 bottom
CV84  0.1U_0402_25V6  [C_0402]  207.68 76.85 0 bottom
CV85  0.01U_0402_16V7K  [C_0402]  205.61 76.85 180 bottom
CV86  0.01U_0402_16V7K  [C_0402]  207.25 72.77 270 bottom
CV87  1U_0603_10V6K  [C_0603]  206.55 70.66 0 bottom
CV88  0.1U_0402_25V6  [C_0402]  206.35 74.91 0 bottom
CV89  0.01U_0402_16V7K  [C_0402]  205.28 72.77 270 bottom
CV90  10U_0603_6.3V6M  [C_0603]  209.29 72.55 0 bottom
CV91  0.1U_0402_25V6  [C_0402]  205.28 81.06 90 bottom
CV92  0.01U_0402_16V7K  [C_0402]  210.03 78.47 0 bottom
CV93  0.01U_0402_16V7K  [C_0402]  203.26 76.22 90 bottom
CV94  10U_0603_6.3V6M  [C_0603]  212.01 80.31 270 bottom
CV95  0.1U_0402_25V6  [C_0402]  203.31 80.36 90 bottom
CV96  0.01U_0402_16V7K  [C_0402]  209.86 74.13 90 bottom
CV97  0.01U_0402_16V7K  [C_0402]  203.88 72.77 270 bottom
CV98  0.01U_0402_16V7K  [C_0402]  208.39 81.06 90 bottom
CV99  0.01U_0402_16V7K  [C_0402]  210.94 76.16 90 bottom
CV100  0.1U_0402_25V6  [C_0402]  210.74 74.08 0 bottom
CV101  10U_0603_6.3V6M  [C_0603]  212.01 75.93 90 bottom
CV102  0.1U_0402_10V7K  [C_0402]  209.28 68.42 90 top
CV103  0.1U_0402_10V7K  [C_0402]  208.39 68.42 90 top
CV104  0.1U_0402_10V7K  [C_0402]  207.5 68.42 90 top
CV105  0.1U_0402_10V7K  [C_0402]  206.61 68.42 90 top
CV106  0.1U_0402_10V7K  [C_0402]  205.72 68.42 90 top
CV107  0.1U_0402_10V7K  [C_0402]  204.83 68.42 90 top
CV108  0.1U_0402_10V7K  [C_0402]  203.95 68.42 90 top
CV109  0.1U_0402_10V7K  [C_0402]  203.06 68.42 90 top
CV110  0.1U_0402_10V7K  [C_0402]  210.17 68.42 90 top
CV111  0.1U_0402_10V7K  [C_0402]  211.06 68.42 90 top
CV113  22P_0402_50V8J  [C_0402]  216.52 71.67 0 top
CV114  0.1U_0402_25V6  [C_0402]  193.93 73.81 90 bottom
CV115  22P_0402_50V8J  [C_0402]  213.34 70.48 270 top
CV116  470P_0402_50V7K  [C_0402]  220.4 75.64 0 bottom
CV117  470P_0402_50V7K  [C_0402]  220.4 76.52 0 bottom
CV118  0.1U_0402_25V6  [C_0402]  209.9 82.66 0 bottom
CV119  0.1U_0402_10V7K  [C_0402]  202.88 85.14 180 bottom
CV120  0.1U_0402_10V7K  [C_0402]  202.88 86.02 180 bottom
CV121  0.1U_0402_25V6  [C_0402]  200.71 86.97 0 bottom
CV122  0.1U_0402_10V7K  [C_0402]  201.17 81.84 270 bottom
CV123  0.1U_0402_10V7K  [C_0402]  202.05 81.84 270 bottom
CV145  0.1U_0402_25V6  [C_0402]  233.66 34.79 270 top
CV146  0.1U_0402_25V6  [C_0402]  234.55 34.79 270 top
CV147  0.1U_0402_25V6  [C_0402]  235.2 31.99 270 top
CV148  0.1U_0402_25V6  [C_0402]  236.09 31.99 270 top
CV149  0.1U_0402_25V6  [C_0402]  232.27 32.95 270 top
CV150  0.1U_0402_25V6  [C_0402]  233.16 32.95 270 top
CV152  0.1U_0402_25V6  [C_0402]  236.71 29.78 270 top
CV153  0.1U_0402_25V6  [C_0402]  237.6 29.78 270 top
CV156  0.1U_0402_25V6  [C_0402]  238.24 28 270 top
CV157  0.1U_0402_25V6  [C_0402]  239.12 28 270 top
CV374  2200P_0402_50V7K  [C_0402]  199.83 65.61 0 bottom
CV501  0.1U_0402_10V7K  [C_0402]  287.14 77.01 180 bottom
CV502  0.1U_0402_10V7K  [C_0402]  287.14 76.12 180 bottom
CV503  0.1U_0402_10V7K  [C_0402]  287.14 73.32 180 bottom
CV504  0.1U_0402_10V7K  [C_0402]  287.14 72.44 180 bottom
CV505  0.1U_0402_10V7K  [C_0402]  287.14 78.85 180 bottom
CV506  0.1U_0402_10V7K  [C_0402]  287.14 77.96 180 bottom
CV507  0.1U_0402_10V7K  [C_0402]  287.14 75.17 180 bottom
CV508  0.1U_0402_10V7K  [C_0402]  287.14 74.28 180 bottom
CV509  .01U_0402_16V7K  [C_0402]  286.45 65.2 270 top
CV510  0.1U_0402_16V4Z  [C_0402]  282.51 65.37 90 top
CV512  0.1U_0402_10V7K  [C_0402]  284.92 63.04 270 bottom
CV513  0.1U_0402_10V7K  [C_0402]  284.03 63.04 270 bottom
CV514  0.1U_0402_25V6  [C_0402]  287.59 67.8 270 bottom
CV600  0.1U_0402_25V6  [C_0402]  229.17 73.77 270 bottom
CV601  0.1U_0402_25V6  [C_0402]  220.6 73.3 90 top
CV602  0.1U_0402_25V6  [C_0402]  222.5 68.8 90 bottom
CV603  0.01U_0402_16V7K  [C_0402]  232.66 68.67 90 top
CV604  0.01U_0402_16V7K  [C_0402]  232.85 71.72 90 top
CV605  2.2U_0402_6.3V6M  [C_0402]  224.03 73.77 270 bottom
CV606  0.1U_0402_25V6  [C_0402]  229.55 76.69 270 top
CV607  0.1U_0402_25V6  [C_0402]  228.66 76.69 270 top
CV608  0.1U_0402_25V6  [C_0402]  227.77 76.69 270 top
CV609  0.1U_0402_25V6  [C_0402]  226.88 76.69 270 top
CV610  0.1U_0402_25V6  [C_0402]  225.99 76.69 270 top
CV611  0.1U_0402_25V6  [C_0402]  225.1 76.69 270 top
CV612  0.1U_0402_25V6  [C_0402]  224.22 76.69 270 top
CV613  0.1U_0402_25V6  [C_0402]  223.33 76.69 270 top
CZ1  0.1U_0402_25V6  [C_0402]  104.09 89.97 180 top
CZ2  0.1U_0402_16V4Z  [C_0402]  97.98 93.64 0 top
CZ4  0.1U_0402_25V6  [C_0402]  191.15 69 180 top
CZ5  4700P_0402_25V7K  [C_0402]  186.32 69 180 bottom
CZ6  2200P_0402_50V7K  [C_0402]  190.5 77.14 270 top
CZ7  2200P_0402_50V7K  [C_0402]  186.51 77.25 180 top
CZ9  0.1U_0402_25V6  [C_0402]  187.89 80.35 90 top
CZ13  0.1U_0402_10V7K  [C_0402]  228.65 26.26 0 top
CZ14  0.1U_0402_10V7K  [C_0402]  228.65 25.37 0 top
CZ15  0.1U_0402_25V6  [C_0402]  241.31 32.8 180 top
CZ16  0.047U_0402_16V4Z  [C_0402]  241.31 33.76 180 top
CZ17  0.1U_0402_25V6  [C_0402]  245.22 11.53 90 top
CZ18  0.1U_0402_25V6  [C_0402]  243.32 11.53 90 top
CZ19  4.7U_0603_6.3V6K  [C_0603]  241.55 31.72 180 top
CZ20  0.047U_0402_16V4Z  [C_0402]  244.27 12.44 270 top
CZ21  0.1U_0402_10V7K  [C_0402]  229.98 22.58 0 top
CZ22  0.1U_0402_10V7K  [C_0402]  229.98 21.69 0 top
CZ23  470P_0402_50V7K  [C_0402]  239.28 58.46 180 top
CZ24  0.1U_0402_10V7K  [C_0402]  239.28 56.68 180 top
CZ25  220P_0402_50V7K  [C_0402]  162.75 85.97 270 top
CZ30  10P_0402_50V8J  [C_0402]  247.32 24.16 90 top
CZ31  10P_0402_50V8J  [C_0402]  246.43 24.16 90 top
CZ32  0.1U_0402_10V7K  [C_0402]  231.82 64.55 0 top
CZ33  0.1U_0402_10V7K  [C_0402]  231.82 63.66 0 top
CZ34  0.1U_0402_25V6  [C_0402]  269.97 34.72 0 top
CZ35  0.01U_0402_16V7K  [C_0402]  270.43 36.3 0 top
CZ36  0.1U_0402_10V7K  [C_0402]  245.17 28.81 180 top
CZ37  470P_0402_50V7K  [C_0402]  245.17 29.7 180 top
CZ38  10U_0603_6.3V6M  [C_0603]  161.59 83.87 90 top
CZ39  0.1U_0402_10V7K  [C_0402]  193.6 48.32 270 top
CZ40  0.1U_0402_10V7K  [C_0402]  222.12 63.99 270 top
CZ41  470P_0402_50V7K  [C_0402]  222.36 65.7 0 top
CZ42  470P_0402_50V7K  [C_0402]  225.12 65.7 180 top
CZ43  0.1U_0402_10V7K  [C_0402]  226.04 65.51 0 top
CZ44  0.1U_0402_10V7K  [C_0402]  218.49 39.3 270 top
CZ45  470P_0402_50V7K  [C_0402]  217.53 39.3 270 top
CZ46  1000P_0402_50V7K  [C_0402]  216.58 39.3 270 top
CZ47  0.1U_0402_10V7K  [C_0402]  215.76 36.87 0 top
CZ48  0.1U_0402_25V6  [C_0402]  263.84 55.67 180 top
CZ49  470P_0402_50V7K  [C_0402]  239.28 57.57 180 top
CZ50  0.1U_0402_10V7K  [C_0402]  239.28 59.35 180 top
CZ51  0.047U_0402_16V4Z  [C_0402]  242.63 72.92 90 top
CZ52  0.047U_0402_16V4Z  [C_0402]  242.41 54.53 0 top
CZ53  33P_0402_50V8J  [C_0402]  242.41 53.64 0 top
CZ54  22U_0603_6.3V6M  [C_0603]  241.11 52.58 270 top
CZ55  33P_0402_50V8J  [C_0402]  241.68 72.92 90 top
CZ57  150U_B2_6.3VM_R35M  [C_B2]  234.92 46.27 90 bottom
CZ58  0.1U_0402_10V7K  [C_0402]  232.8 61.51 180 top
CZ59  0.1U_0402_10V7K  [C_0402]  232.8 60.62 180 top
CZ64  470P_0402_50V7K  [C_0402]  194.55 47.4 90 top
CZ65  33P_0402_50V8J  [C_0402]  232.95 86.68 0 bottom
CZ66  33P_0402_50V8J  [C_0402]  232.97 87.62 0 bottom
CZ67  33P_0402_50V8J  [C_0402]  232.99 89.22 0 bottom
D19  -  [RB751S40T1G_SOD523-2]  182.62 101.04 270 bottom
D20  -  [L30ESD24VC3-2_SOT23-3]  129.02 91.71 0 top
DA1  AZ5123-02S.R7G_SOT23-3  [L03ESDL5V0CC3-2_SOT23-3]  16.4 17.25 270 top
DA2  -  [L03ESDL5V0CC3-2_SOT23-3]  17.28 15.44 180 bottom
DA3  AZ5123-02S.R7G_SOT23-3  [L03ESDL5V0CC3-2_SOT23-3]  18.49 13.32 90 top
DA4  -  [RB751S40T1G_SOD523-2]  24 14.2 0 top
DA5  -  [RB751S40T1G_SOD523-2]  24 15.53 0 top
DA6  -  [L03ESDL5V0CC3-2_SOT23-3]  3.81 7.51 180 bottom
DA7  -  [L03ESDL5V0CC3-2_SOT23-3]  7.81 7.51 180 bottom
DE1  -  [RB751S40T1G_SOD523-2]  63.65 85.51 180 top
DI1  -  [L05ESDL5V0NA-4_SLP2510P8-10-9]  85.37 92.03 180 top
DI2  -  [AZC199-02SPR7G_SOT23-3]  77.54 91.74 270 top
DI3  -  [AZC199-02SPR7G_SOT23-3]  243.38 92.53 0 bottom
DI4  -  [L05ESDL5V0NA-4_SLP2510P8-10-9]  285.63 60.53 90 bottom
DI5  -  [AZC199-02SPR7G_SOT23-3]  285.19 55.86 270 bottom
DI6  -  [L05ESDL5V0NA-4_SLP2510P8-10-9]  238.39 92.63 180 bottom
DV1  -  [BAT54CW_SOT323-3]  117.15 85.23 0 top
DV2  -  [BAT54CW_SOT323-3]  119.63 85.23 0 top
DV3  -  [BAT54CW_SOT323-3]  120.8 89.57 90 top
DV4  -  [AZC199-02SPR7G_SOT23-3]  98.51 94.54 180 bottom
DZ1  -  [RB751S40T1G_SOD523-2]  241.36 27.85 0 top
DZ2  -  [RB751S40T1G_SOD523-2]  241.36 28.99 0 top
DZ3  -  [RB751S40T1G_SOD523-2]  271.01 22.77 0 top
DZ4  -  [RB751S40T1G_SOD523-2]  271.33 25.12 270 top
DZ5  -  [RB751S40T1G_SOD523-2]  240.22 69.57 90 top
DZ6  -  [RB751S40T1G_SOD523-2]  242.12 65.06 90 top
FD1  FIDUCIAL MARK~D  [FIDUCIAL_C40M80]  13.32 11.51 0 top
FD2  FIDUCIAL MARK~D  [FIDUCIAL_C40M80]  300.67 91.48 0 top
FD3  FIDUCIAL MARK~D  [FIDUCIAL_C40M80]  18.98 11.91 180 bottom
FD4  FIDUCIAL MARK~D  [FIDUCIAL_C40M80]  300.67 91.48 180 bottom
H1  -  [H_2P3]  56.7 105.85 0 top
H2  -  [H_2P3]  118.7 105.85 0 top
H3  -  [H_2P3]  184.7 105.85 0 top
H4  -  [H_2P3]  230.2 105.85 0 top
H5  -  [H_5P5N]  258.95 98 0 top
H6  -  [H_2P3]  291.3 90.65 0 top
H7  -  [H_2P3]  69.98 61.55 0 top
H9  -  [H_2P3]  283.7 49.65 0 top
H10  -  [H_2P3]  240.35 43.65 0 top
H11  -  [H_2P3]  299.7 11.15 0 top
H12  -  [H_3P6]  236.8 8.1 0 top
H13  -  [H_2P3]  151.7 15.65 0 top
H14  -  [H_3P5]  122.5 74.57 0 top
H15  -  [H_3P5]  122.5 52.43 0 top
H16  -  [H_3P5]  177.82 52.43 0 top
H17  -  [H_3P5]  177.82 74.57 0 top
H18  -  [H_5P2X2P6N]  14.55 8.15 0 top
H19  -  [H_3P2]  266.87 24.6 0 top
H20  -  [H_3P2]  277.87 63.56 0 top
H21  -  [H_2P3]  135.67 82 0 top
H22  -  [H_3P3]  92.2 88.9 0 top
H23  -  [H_2P6N]  294.32 11.15 0 top
JAPS1  ACES_50506-01841-P01  [ACES_50506-01841-P01_18P]  300.75 30.19 270 top
JDEG1  HB_A531015-SCHR21  [HB_A531015-SCHR21_10P]  298.14 40.63 270 top
JDIMM1  LCN_DAN06-K4406-0103  [LCN_DAN06-K4406-0103_204P]  79 16.43 180 bottom
JDIMM2  LCN_DAN06-K4406-0103  [LCN_DAN06-K4406-0103_204P]  160.5 16.43 180 bottom
JDOCK1  JAE_WD2F144WB5R400  [JAE_WD2F144WB5R400_144P]  132.95 97.05 0 bottom
JEDP1  ACES_50398-04041-001  [ACES_50398-04041-001_40P]  98.96 90.3 0 bottom
JFAN1  ACES_50271-0040N-001  [ACES_50271-0040N-001_4P]  62.04 87.97 134.5 bottom
JHDMI1  CONCR_099BKAC19YBLCNF  [CONCR_099BKAC19YBLCNF_19P-T]  210.7 100.07 0 bottom
JHP1  SINGA_2SJ3080-039111F  [SINGA_2SJ3080-039111F_6P-T]  11.55 15.24 270 bottom
JKBTP1  E-T_6705K-Y16N-00L  [E-T_6705K-Y16N-00L_16P]  244.5 23.1 270 top
JLED1  E-T_6705K-Y10N-00L  [E-T_6705K-Y10N-00L_10P-T]  266.15 11.45 0 top
JLOM1  SANTA_130456-511  [SANTA_130456-511_13P-T]  268.88 97.28 0 bottom
JLPDE1  HB_A531015-SCHR21  [HB_A531015-SCHR21_10P]  270.56 60.05 0 top
JMDP1  ACON_MAR2B-20K1803  [ACON_MAR2B-20K1803_20P-T]  293.95 77.55 270 bottom
JNGFF1  BELLW_80148-3221  [BELLW_80148-3221_67P-T]  233.34 33.85 270 bottom
JNGFF2  BELLW_80149-4221  [BELLW_80149-4221_67P-T]  232.34 72.85 270 bottom
JRTC1  TYCO_2-1775293-2~D  [TYCO_2-1775293-2_2P]  296.7 5.95 180 top
JSATA1  STARC_115B20-000000-G2-R  [STARC_115B20-000000-G2-R_20P-T]  258.94 6.75 0 bottom
JSD1  T-SOL_156-2000302608_NR  [T-SOL_156-2000302608_19P_NR-S]  271.72 36.87 270 bottom
JSIM1  T-SOL_159-1201300600  [T-SOL_159-1201300600_8P-T]  230.91 85.6 90 bottom
JSPI1  E-T_6700K-Y20N-00L  [E-T_6700K-Y20N-00L_20P]  179.38 83.42 180 bottom
JSPK1  ACES_50279-0040N-001  [ACES_50279-0040N-001_4P]  4.21 12.2 0 top
JTAG1  @SHORT PADS~D  [SHORTPADS]  262.95 30.72 90 top
JUSB1  C-K_26210-8K1A-02  [C-K_26210-8K1A-02_9P-T]  88.2 95.87 0 bottom
JUSB2  C-K_26210-8K1A-02  [C-K_26210-8K1A-02_9P-T]  246.3 95.87 0 bottom
JUSB3  SINGA_2UB1641-000111F  [SINGA_2UB1641-000111F_9P-T]  288.8 52.65 270 bottom
JUSH1  E-T_6705K-Y20N-00L  [E-T_6705K-Y20N-00L_20P]  260.17 10.16 0 top
JXDP1  SAMTE_BSH-030-01-L-D-A  [SAMTE_BSH-030-01-L-D-A_60P]  78.15 60.7 270 top
LA2  BLM15BD601SN1D_2P  [MURAT_BLM15BD601SN1D_2P]  21.32 13.63 270 top
LA3  BLM15BD601SN1D_2P  [MURAT_BLM15BD601SN1D_2P]  21.01 16.8 180 top
LA5  BLM15PX600SN1D_2P  [MURAT_BLM15PX600SN1D_2P]  26.21 20.58 90 top
